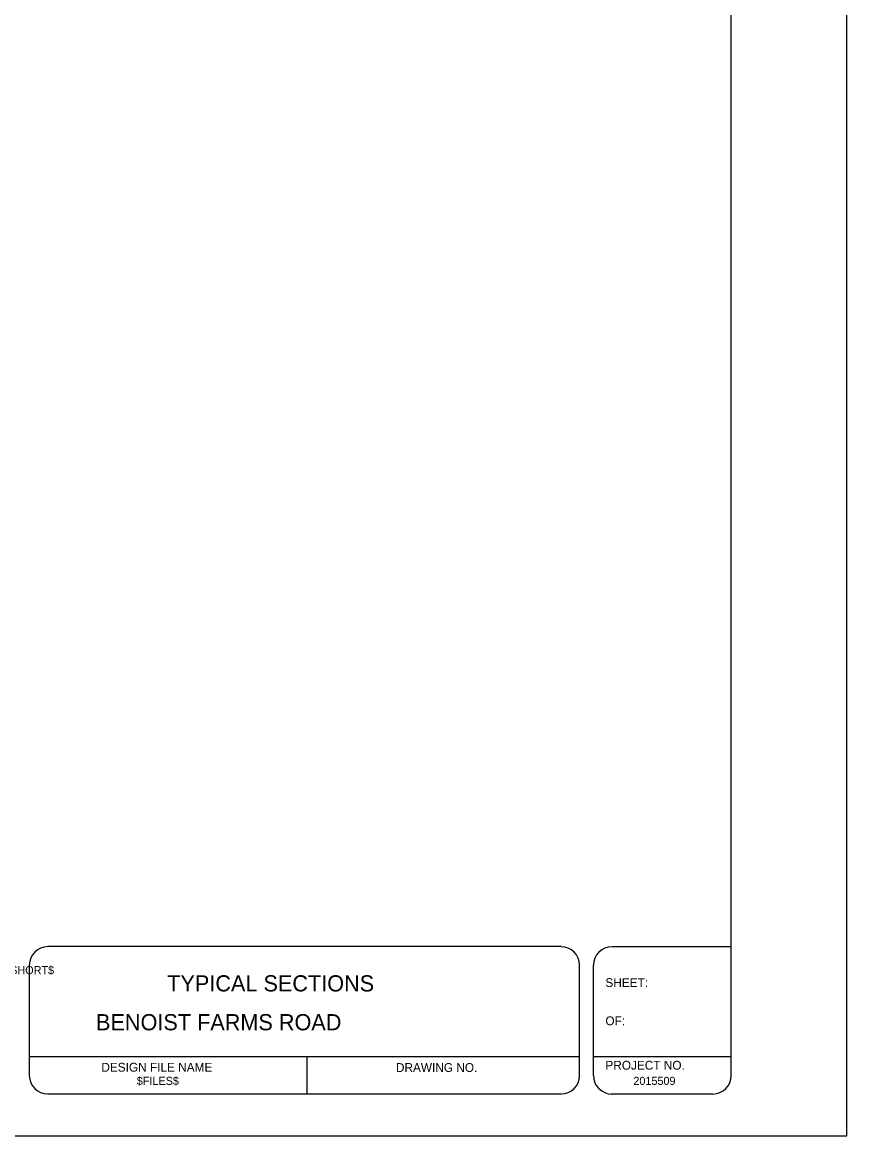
# Model space of a CAD drawing. Extents: x -0.6 to 16, y -0.9 to 9.7.
# Drawn here: x 12.02 to 15.95, y -0.9 to 4.4 of the extents above; entities that cross this region are included whole.
import ezdxf

# ---------------------------------------------------------------- set-up
doc = ezdxf.new("R2010")
doc.units = 0
doc.layers.add('Default', color=7, linetype='Continuous')
doc.layers.add('PlotBorder_dp', color=7, linetype='Continuous')

msp = doc.modelspace()

# ---------------------------------------------------------------- linework, layer by layer
at = {"layer": 'Default'}
for p, q in [((15.4, -0.6133), (15.4, 9.5065)), ((14.5898, 0), (12.146, 0)), ((14.8324, 0), (15.4, 0)), ((12.0578, -0.0882), (12.0578, -0.6131)), ((14.678, -0.6135), (14.678, -0.0884)), ((14.7442, -0.6135), (14.7442, -0.0884)), ((14.6769, -0.5241), (12.0568, -0.5241)), ((13.3801, -0.7005), (13.3801, -0.5241)), ((15.4, -0.5241), (14.7475, -0.5241)), ((14.5898, -0.7014), (12.146, -0.7014)), ((15.3118, -0.7015), (14.8271, -0.7015))]:
    msp.add_line(p, q, dxfattribs=at)
for centre, major_axis, start_param, end_param in [((12.146, -0.0882), (0, 0.0882), 0, 1.570796), ((14.5898, -0.0884), (0, 0.0882), 4.712389, 6.283185), ((14.8324, -0.0884), (0, -0.0882), 3.141593, 4.712389), ((12.146, -0.6131), (0, -0.0882), 4.712389, 6.283185), ((14.5898, -0.6131), (0, 0.0882), 3.141593, 4.712389), ((14.8324, -0.6135), (0, -0.0882), 4.712389, 6.283185), ((15.3118, -0.6133), (0, -0.0882), 0, 1.570796)]:
    msp.add_ellipse(centre, major_axis=major_axis, ratio=0.999927, start_param=start_param, end_param=end_param, dxfattribs=at)
at = {"layer": 'PlotBorder_dp'}
msp.add_lwpolyline([(-0.55, -0.9), (15.95, -0.9), (15.95, 9.7), (-0.55, 9.7)], close=True, dxfattribs=at)

# ---------------------------------------------------------------- texts
at = {"layer": 'Default'}
for s, height, p in [('$SCALESHORT$', 0.038546, (11.7691, -0.1311)), ('TYPICAL SECTIONS', 0.077091, (12.7144, -0.2133)), ('SHEET:', 0.04207, (14.8009, -0.1922)), ('   BENOIST FARMS ROAD   ', 0.077091, (12.2895, -0.3982)), ('OF:', 0.04207, (14.8009, -0.374)), ('DESIGN FILE NAME', 0.042066, (12.4009, -0.5951)), ('DRAWING NO.', 0.042066, (13.8035, -0.5964)), ('PROJECT NO.', 0.042066, (14.8009, -0.5856)), ('$FILES$', 0.03855, (12.5694, -0.6581)), ('2015509', 0.03855, (14.9341, -0.6581))]:
    msp.add_text(s, height=height, dxfattribs=at).set_placement(p)

doc.saveas('drawing.dxf')
